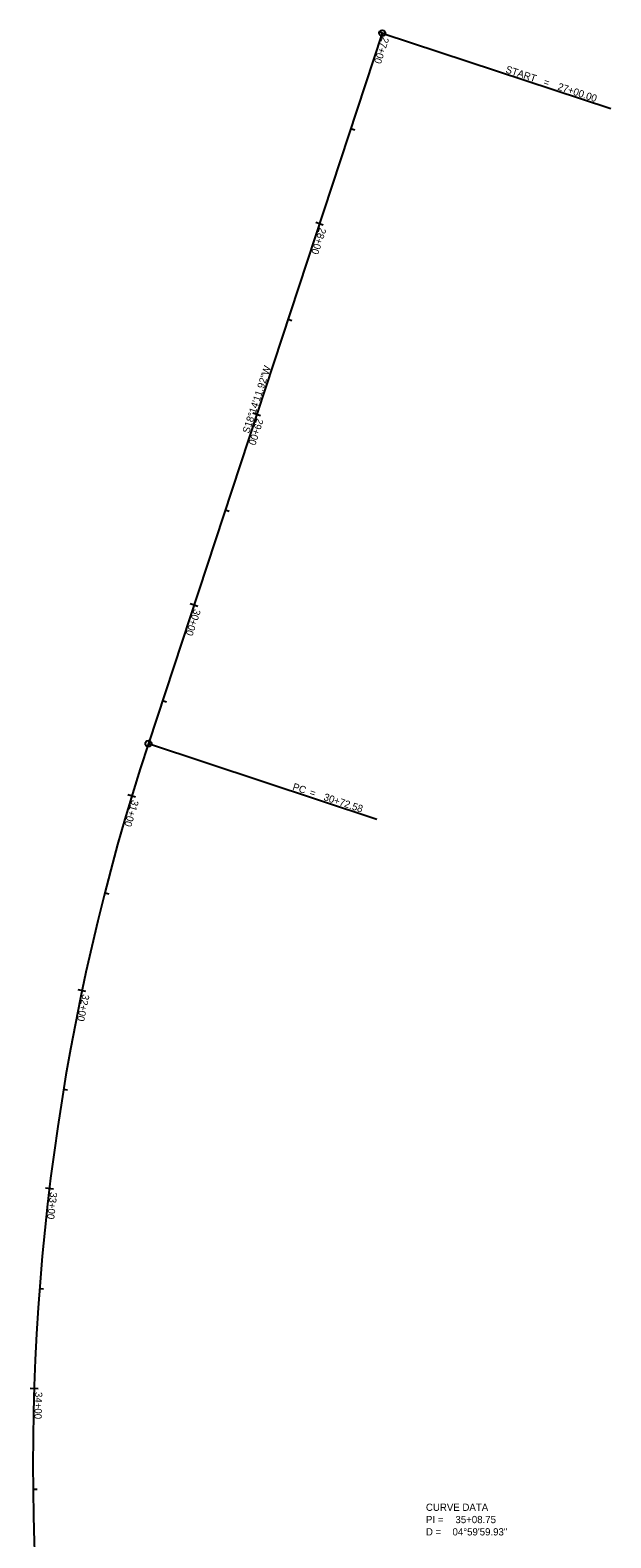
# Model space of a CAD drawing. Extents: x 1733827 to 1734180, y 466749 to 468257.
# Drawn here: x 1733827 to 1734117, y 467506 to 468257 of the extents above; entities that cross this region are included whole.
import ezdxf

# ---------------------------------------------------------------- set-up
doc = ezdxf.new("R2010")
doc.units = 0
for name, color, linetype in [('D_Roadway_Centerline', 7, 'Continuous'), ('D_Roadway_Centerline_Bearings', 7, 'Continuous'), ('D_Roadway_Centerline_CurveData', 7, 'Continuous'), ('D_Roadway_Centerline_Flags', 7, 'Continuous'), ('D_Roadway_Centerline_Text', 7, 'Continuous')]:
    doc.layers.add(name, color=color, linetype=linetype)

msp = doc.modelspace()

# ---------------------------------------------------------------- linework, layer by layer
at = {"layer": 'D_Roadway_Centerline'}
msp.add_line((1734002.97, 468255.18), (1733886.38, 467901.32), dxfattribs=at)
msp.add_arc((1734974.74, 467542.71), 1145.92, 161.76336, 203.4402, dxfattribs=at)
at = {"layer": 'D_Roadway_Centerline_Flags'}
for p, q in [((1734002.97, 468255.18), (1734002.97, 468255.18)), ((1734002.97, 468255.18), (1734116.94, 468217.63)), ((1734116.94, 468217.63), (1734116.94, 468217.63)), ((1733886.38, 467901.32), (1733886.38, 467901.32)), ((1733886.38, 467901.32), (1734000.35, 467863.77)), ((1734000.35, 467863.77), (1734000.35, 467863.77))]:
    msp.add_line(p, q, dxfattribs=at)
for centre in [(1734002.97, 468255.18), (1733886.38, 467901.32)]:
    msp.add_circle(centre, 1.5, dxfattribs=at)
at = {"layer": 'D_Roadway_Centerline_Text'}
for p, q in [((1734004.88, 468254.56), (1734001.08, 468255.81)), ((1733987.32, 468207.7), (1733989.23, 468207.07)), ((1733973.59, 468159.58), (1733969.79, 468160.83)), ((1733956.03, 468112.72), (1733957.94, 468112.09)), ((1733942.29, 468064.6), (1733938.49, 468065.85)), ((1733924.74, 468017.74), (1733926.65, 468017.11)), ((1733911, 467969.62), (1733907.2, 467970.88)), ((1733893.44, 467922.76), (1733895.35, 467922.14)), ((1733880.03, 467874.59), (1733876.2, 467875.75)), ((1733864.65, 467827.02), (1733866.6, 467826.53)), ((1733855.27, 467777.92), (1733851.36, 467778.74)), ((1733844.09, 467729.19), (1733846.08, 467728.87)), ((1733839.03, 467679.46), (1733835.06, 467679.94)), ((1733832.14, 467629.94), (1733834.15, 467629.79)), ((1733831.44, 467579.95), (1733827.44, 467580.08)), ((1733828.89, 467530.03), (1733830.9, 467530.05))]:
    msp.add_line(p, q, dxfattribs=at)

# ---------------------------------------------------------------- texts
at = {"layer": 'D_Roadway_Centerline_Bearings'}
msp.add_text('S18°14\'11.92"W', height=3.6, rotation=71.76336, dxfattribs=at).set_placement((1733936.56, 468055.54))
at = {"layer": 'D_Roadway_Centerline_CurveData'}
for s, p in [('CURVE DATA', (1734024.76, 467519.17)), ('PI = ', (1734024.76, 467513.05)), ('D = ', (1734024.76, 467506.93)), ('04°59\'59.93"', (1734038, 467506.93)), ('35+08.75', (1734039.46, 467513.05))]:
    msp.add_text(s, height=3.6, dxfattribs=at).set_placement(p)
at = {"layer": 'D_Roadway_Centerline_Flags'}
for s, p in [('START', (1734064.14, 468235.66)), (' = ', (1734081.74, 468229.86)), ('27+00.00', (1734090.08, 468227.11)), ('PC', (1733957.96, 467878.37)), (' = ', (1733965.1, 467876.01)), ('30+72.58', (1733973.45, 467873.26))]:
    msp.add_text(s, height=3.6, rotation=341.76336, dxfattribs=at).set_placement(p)
at = {"layer": 'D_Roadway_Centerline_Text'}
for s, rotation, p in [('27+00', 251.76336, (1734003.05, 468253.52)), ('28+00', 251.76336, (1733971.76, 468158.54)), ('29+00', 251.76336, (1733940.47, 468063.56)), ('30+00', 251.76336, (1733909.17, 467968.58)), ('31+00', 253.13447, (1733878.23, 467873.51)), ('32+00', 258.13445, (1733853.57, 467776.68)), ('33+00', 263.13443, (1733837.45, 467678.08)), ('34+00', 268.13441, (1733829.98, 467578.44))]:
    msp.add_text(s, height=3.6, rotation=rotation, dxfattribs=at).set_placement(p)

doc.saveas('drawing.dxf')
